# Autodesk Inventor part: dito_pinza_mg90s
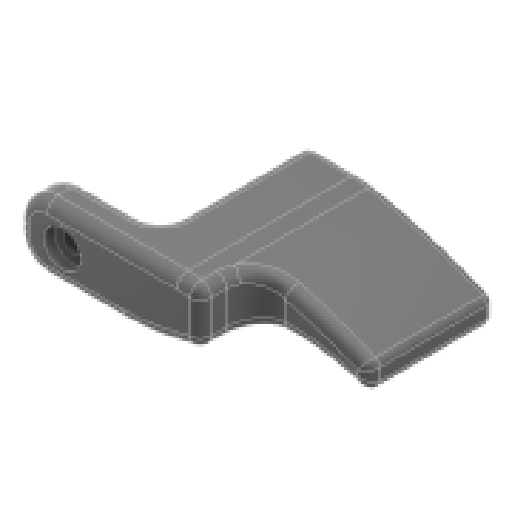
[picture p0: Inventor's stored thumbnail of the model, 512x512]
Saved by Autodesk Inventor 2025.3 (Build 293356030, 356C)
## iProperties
Created: 2026-03
Part Number: dito_pinza_mg90s
Material: Plastica ABS
Document SubType Name: Modeling
Designer: Ryzen5700u
Density: 1.06 g/cm^3
Appearance: Liscia - Nero
Author: Ryzen5700u
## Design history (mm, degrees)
sketch "Schizzo1"
  geometry: L1 (-6.045, 3.974)-(8.415, 2.335) reference; L2 (-12.5, -4.5)-(27.5, -4.5); L3 (27.5, -4.5)-(27.5, 4.5); L4 (27.5, 4.5)-(-12.5, 4.5); L5 (-12.5, 4.5)-(-12.5, -4.5); L6 (-6.5, 0)-(-16.812, 0); L7 (-4.9, 3)-(9.143, 1.995) reference; L8 (9.143, -1.995)-(-4.9, -3) reference; L9 (-4.889, 3.15)-(9.153, 2.145); L10 (9.153, -2.145)-(-4.889, -3.15); L11 (-12.5, -4.5)-(27.5, -4.5); L12 (27.5, -4.5)-(27.5, -5.5); L13 (27.5, -5.5)-(-12.5, -5.5); L14 (-12.5, -5.5)-(-12.5, -4.5); C1 r 3.55 at (-6.5, 0); A1 r 4 centre (-6.5, 0) between (-6.045, 3.974) and (-6.045, -3.974) reference; A2 r 3.4 centre (-6.5, 0) between (-4.9, 3) and (-4.9, -3); A3 r 2 centre (9, 0) between (9.143, -1.995) and (9.143, 1.995) reference; A4 r 2.15 centre (9, 0) between (9.153, -2.145) and (9.153, 2.145); 3 further points
  constraints: 26 end point, 4 centre point, 4 parallel, 4 point on circle, 3 horizontal, 2 perpendicular, 1 coincident, 11 other
  dimensions: "d1" = 40 distance of L4.end L3.end; "d4" = 9 distance of L2.end L3.end; "d35" = 6.8 diameter of A2; "d36" = 0.15 radial gap between concentric circles of A3 A4; "d37" = 0.15 radial gap between concentric circles of A2 C1; "d63" = 6 distance from line of L5 A1.centre; "d72" = 1 distance of L11.end L12.end
extrude "Estrusione1" new body sketch "Schizzo1" distance "d2" = 2; taper "d3" = 0 deg
sketch "Schizzo2"
  geometry: L1 (-12.5, 4.5)-(27.5, 4.5) reference; L2 (27.5, -4.5)-(-12.5, -4.5); L3 (-12.5, -4.5)-(-12.5, 4.5); L4 (-12.5, 4.5)-(27.5, 4.5); L5 (27.5, 4.5)-(27.5, -4.5); 2 further points
  constraints: 8 end point, 2 parallel, 1 horizontal, 1 perpendicular
node "Piano di lavoro1"
node "Piano di lavoro2"
extrude "Estrusione2" join sketch "Schizzo2" distance "d5" = 1.8; taper "d6" = 0 deg
hole "Foro3" sketch "Schizzo1" diameter "d28" = 2.7; stored, may be unused: countersink angle "d32" = 90 deg, drill point angle "d34" = 118 deg; dims "d29" = 6, "d30" = 5.5, "d31" = 2.9, "d33" = 8
fillet "Raccordo2" dims "d38" = 4
sketch "Schizzo5"
  geometry: L1 (-27.5, 4.5)-(8.5, 4.5) reference; L2 (-27.5, 4.5)-(-27.5, -4.5) reference; L3 (8.5, 4.5)-(-27.5, 4.5) reference; L4 (-27.5, 4.5)-(-27.5, -4.5) reference; L5 (-27.5, -4.5)-(8.5, -4.5) reference; L6 (12.5, -0.5)-(12.5, 0.5) reference; L7 (-9.153, 2.145)-(4.858, 3.147) reference; L8 (4.858, -3.147)-(-9.153, -2.145) reference; L9 (-27.5, -4.5)-(8.5, -4.5) reference; A1 r 74.354 centre (2.806, -68.708) between (15.809, 4.5) and (-27.5, -0.811); A2 r 4 centre (8.5, 0.5) between (12.5, 0.5) and (8.5, 4.5) reference; A3 r 4 centre (8.5, -0.5) between (8.5, -4.5) and (12.5, -0.5) reference; A4 r 2.15 centre (-9, 0) between (-9.153, 2.145) and (-9.153, -2.145) reference; A5 r 3.55 centre (6.5, 0) between (4.858, -3.147) and (4.858, 3.147) reference; A6 r 30 centre (-16.848, -32.545) between (-6.195, -4.5) and (-27.5, -4.5); 5 further points
  constraints: 4 point on circle, 4 point on line, 2 centre point
  dimensions: "d75" = 30 radius of A6
extrude "Estrusione3" cut sketch "Schizzo5" extent not by distance; stored distance "d39" = 1; taper "d40" = 0 deg
sketch "Schizzo6"
  geometry: C1 r 1.35 at (-6.5, 0) reference; 2 further points
  constraints: 1 coincident
hole "Foro4" sketch "Schizzo6" at (-6.5, 0) diameter "d41" = 2.7; stored, may be unused: countersink angle "d45" = 90 deg, drill point angle "d47" = 118 deg; dims "d42" = 6, "d43" = 5, "d44" = 0.5, "d46" = 8
fillet "Raccordo3" dims "d51" = 1
fillet "Raccordo4" dims "d52" = 30
sketch "Schizzo8"
  geometry: L1 (-1.657, -4.5)-(8.5, -4.5) reference; L2 (12.5, -0.5)-(12.5, 0.5) reference; L3 (8.5, 4.5)-(-10.197, 4.5) reference; L4 (-27.5, -1.463)-(-27.5, -3.086) reference; L5 (-9.153, 2.145)-(4.858, 3.147) reference; L6 (4.858, -3.147)-(-9.153, -2.145) reference; L7 (-2, 5.49)-(-2, -4.498); A1 r 30 centre (-1.657, 25.5) between (-9.252, -3.523) and (-1.657, -4.5) reference; A2 r 4 centre (8.5, -0.5) between (8.5, -4.5) and (12.5, -0.5) reference; A3 r 4 centre (8.5, 0.5) between (12.5, 0.5) and (8.5, 4.5) reference; A4 r 74.354 centre (2.806, -68.708) between (-10.197, 4.5) and (-26.9, -0.546) reference; A5 r 1 centre (-26.5, -1.463) between (-26.9, -0.546) and (-27.5, -1.463) reference; A6 r 1 centre (-26.5, -3.086) between (-27.5, -3.086) and (-26.189, -4.036) reference; A7 r 30 centre (-16.848, -32.545) between (-9.252, -3.523) and (-26.189, -4.036) reference; A8 r 2.15 centre (-9, 0) between (-9.153, 2.145) and (-9.153, -2.145) reference; A9 r 3.55 centre (6.5, 0) between (4.858, -3.147) and (4.858, 3.147) reference; 4 further points
  constraints: 2 end point, 2 point on circle, 1 vertical
  dimensions: "d53" = 2 distance from line of point (0, 0) L7
  node "Linea chiusa proiettata2"
node "Piano di lavoro3"
extrude "Estrusione4" join sketch "Schizzo8" distance "d54" = 5; taper "d55" = 0 deg
sketch "Schizzo9"
  geometry: L1 (-27.5, -1.463)-(-27.5, -3.086) reference; L2 (-2, -4.498)-(-2, -2.657) reference; L3 (-2, 4.202)-(-2, -4.498); L4 (-2, 4.5)-(-10.197, 4.5) reference; L5 (-2, -2.657)-(-9.153, -2.145) reference; L6 (-9.153, 2.145)-(-2, 2.657) reference; L7 (-2, 2.657)-(-2, 4.5) reference; A1 r 1 centre (-26.5, -3.086) between (-27.5, -3.086) and (-26.189, -4.036) reference; A2 r 30 centre (-16.848, -32.545) between (-9.252, -3.523) and (-26.189, -4.036) reference; A3 r 30 centre (-1.657, 25.5) between (-9.252, -3.523) and (-2, -4.498) reference; A4 r 74.354 centre (2.806, -68.708) between (-10.197, 4.5) and (-26.9, -0.546) reference; A5 r 1 centre (-26.5, -1.463) between (-26.9, -0.546) and (-27.5, -1.463) reference; A6 r 2.15 centre (-9, 0) between (-9.153, 2.145) and (-9.153, -2.145) reference; 6 further points
  constraints: 2 end point, 1 vertical
  node "Linea chiusa proiettata3"
node "Piano di lavoro4"
node "Piano di lavoro6"
extrude "Estrusione5" join sketch "Schizzo9" stored distance "d56" = 5; taper "d57" = 0 deg
fillet "Raccordo5" dims "d58" = 2
sketch "Schizzo10"
  geometry: L1 (27.5, -3.086)-(27.5, -1.463) reference; L2 (10.197, 4.5)-(-8.5, 4.5) reference; L3 (-12.5, 0.5)-(-12.5, -0.5) reference; L4 (-8.5, -4.5)-(1.657, -4.5) reference; L5 (2, 4.5)-(2, -4.498) reference; L6 (12.222, -2.904)-(12.222, 4.111); C1 r 2.5 at (-6.5, 0) reference; A1 r 30 centre (1.657, 25.5) between (1.657, -4.5) and (9.252, -3.523) reference; A2 r 30 centre (16.848, -32.545) between (26.189, -4.036) and (9.252, -3.523) reference; A3 r 1 centre (26.5, -3.086) between (26.189, -4.036) and (27.5, -3.086) reference; A4 r 1 centre (26.5, -1.463) between (27.5, -1.463) and (26.9, -0.546) reference; A5 r 74.354 centre (-2.806, -68.708) between (26.9, -0.546) and (10.197, 4.5) reference; A6 r 4 centre (-8.5, 0.5) between (-8.5, 4.5) and (-12.5, 0.5) reference; A7 r 4 centre (-8.5, -0.5) between (-12.5, -0.5) and (-8.5, -4.5) reference; 4 further points
  constraints: 2 end point, 2 point on circle, 1 vertical
  node "Linea chiusa proiettata4"
node "Piano di lavoro5"
extrude "Estrusione6" cut sketch "Schizzo10" stored distance "d59" = 5; taper "d60" = 0 deg
fillet "Raccordo6" dims "d61" = 4
fillet "Raccordo7" dims "d62" = 4
sketch "Schizzo11"
  geometry: L1 (25.5, 7.586)-(25.5, -1.412) reference; L2 (17.303, 7.586)-(25.5, 7.586) reference; L3 (0, 0)-(0, 1.624) reference; L4 (16.979, 11.31)-(28.224, 11.31); L5 (29.224, 10.31)-(29.224, 0.684); L6 (-3.724, -7.465)-(-3.724, 4.65); A1 r 74.354 centre (30.306, -65.622) between (17.303, 7.586) and (0.6, 2.54) reference; A2 r 1 centre (1, 1.624) between (0.6, 2.54) and (0, 1.624) reference; A3 r 1 centre (1, 0) between (0, 0) and (1.311, -0.95) reference; A4 r 30 centre (10.652, -29.459) between (18.248, -0.436) and (1.311, -0.95) reference; A5 r 30 centre (25.843, 28.586) between (18.248, -0.436) and (25.5, -1.412) reference; A6 r 78.078 centre (30.306, -65.622) between (16.979, 11.31) and (-3.724, 4.65); A7 r 5.724 centre (23.5, 0.684) between (23.021, -5.019) and (29.224, 0.684); A8 r 33.724 centre (25.843, 28.586) between (17.305, -4.039) and (23.021, -5.019); A9 r 26.276 centre (10.652, -29.459) between (17.305, -4.039) and (-3.724, -7.465); A10 r 1 centre (28.224, 10.31) between (29.224, 10.31) and (28.224, 11.31)
  constraints: 10 point on circle, 6 end point, 5 centre point, 2 tangent, 4 other
  dimensions: "d69" = 1 radius of A10
extrude "Estrusione7" cut sketch "Schizzo11" distance "d64" = 5; taper "d65" = 0 deg
fillet "Raccordo10" dims "d68" = 1
sketch "Schizzo12"
  geometry: L1 (-9.622, 2.058)-(-9.622, -2.058) reference; L2 (-9.153, -2.145)-(4.858, -3.147) reference; L3 (4.858, 3.147)-(-9.153, 2.145) reference; C1 r 1.35 at (6.5, 0) reference; A1 r 2.15 centre (-9, 0) between (-9.622, -2.058) and (-9.153, -2.145) reference; A2 r 3.55 centre (6.5, 0) between (4.858, -3.147) and (4.858, 3.147) reference; A3 r 2.15 centre (-9, 0) between (-9.153, 2.145) and (-9.622, 2.058) reference; 1 further point
extrude "Estrusione8" cut sketch "Schizzo12" distance "d73" = 4; taper "d74" = 0 deg
fillet "Raccordo13" dims "d76" = 2.5
fillet "Raccordo14" dims "d77" = 12
sketch "Schizzo13"
  geometry: L1 (0, 0)-(0, 1.624) reference; L2 (25.5, 7.586)-(25.5, -1.412) reference; L3 (18.407, 7.586)-(25.5, 7.586) reference; L4 (18.407, 5.786)-(23.5, 5.786); L5 (23.7, 5.586)-(23.7, 0.684); L6 (1.8, 1.084)-(1.8, 1.097); C1 r 0.75 at (9.384, 3.066); C2 r 0.55 at (23.15, 5.236); C3 r 0.511 at (23.189, 1.025); A1 r 12 centre (18.407, -4.414) between (18.407, 7.586) and (16.117, 7.366) reference; A2 r 74.354 centre (30.306, -65.622) between (16.117, 7.366) and (0.6, 2.54) reference; A3 r 1 centre (1, 1.624) between (0.6, 2.54) and (0, 1.624) reference; A4 r 1 centre (1, 0) between (0, 0) and (1.311, -0.95) reference; A5 r 30 centre (10.652, -29.459) between (18.248, -0.436) and (1.311, -0.95) reference; A6 r 30 centre (25.843, 28.586) between (18.248, -0.436) and (25.5, -1.412) reference; A7 r 72.554 centre (30.306, -65.622) between (16.461, 5.599) and (1.8, 1.097); A8 r 10.2 centre (18.407, -4.414) between (18.407, 5.786) and (16.461, 5.599); A9 r 0.2 centre (23.5, 5.586) between (23.7, 5.586) and (23.5, 5.786); A10 r 0.2 centre (23.5, 0.684) between (23.483, 0.485) and (23.7, 0.684); A11 r 28.2 centre (25.843, 28.586) between (18.704, 1.305) and (23.483, 0.485); A12 r 31.8 centre (10.652, -29.459) between (18.704, 1.305) and (1.8, 1.084); 7 further points
  constraints: 12 point on circle, 9 centre point, 6 end point, 6 tangent, 4 other
  dimensions: "d78" = 1.8 radial gap between concentric circles of A2 A7; "d81" = 1.5 diameter of C1
extrude "Estrusione9" cut sketch "Schizzo13" extent not by distance; stored distance "d79" = 0; taper "d80" = 0 deg
fillet "Raccordo15" dims "d82" = 1
fillet "Raccordo16" dims "d83" = 3
fillet "Raccordo17" dims "d84" = 1.5
sketch "Schizzo14"
  geometry: L1 (12.222, -2.904)-(12.222, 4.111) reference; L2 (9.093, 4.5)-(-8.5, 4.5) reference; L3 (-12.5, 0.5)-(-12.5, -0.5) reference; L4 (-8.5, -4.5)-(1.657, -4.5) reference; C1 r 2.5 at (-6.5, 0) reference; A1 r 74.354 centre (-2.806, -68.708) between (12.222, 4.111) and (11.383, 4.279) reference; A2 r 12 centre (9.093, -7.5) between (11.383, 4.279) and (9.093, 4.5) reference; A3 r 4 centre (-8.5, 0.5) between (-8.5, 4.5) and (-12.5, 0.5) reference; A4 r 4 centre (-8.5, -0.5) between (-12.5, -0.5) and (-8.5, -4.5) reference; A5 r 30 centre (1.657, 25.5) between (1.657, -4.5) and (9.252, -3.523) reference; A6 r 30 centre (16.848, -32.545) between (12.222, -2.904) and (9.252, -3.523) reference; 1 further point
extrude "Estrusione10" join sketch "Schizzo14" distance "d85" = 1; taper "d86" = 0 deg
fillet "Raccordo18" dims "d87" = 1.5
fillet "Raccordo19" dims "d88" = 1.5
sketch "Schizzo16"
  geometry: L1 (18.407, 7.586)-(24, 7.586) reference; L2 (0, 0)-(0, 1.624) reference; L3 (25.5, 6.086)-(25.5, 0.146) reference; L4 (18.407, 5.786)-(23.7, 5.786); L5 (23.7, 5.786)-(23.7, 0.468); L6 (1.8, 1.084)-(1.8, 1.097); C1 r 0.705 at (9.033, 3.005); C2 r 0.938 at (22.762, 4.848); C3 r 0.906 at (22.794, 1.463); A1 r 1.5 centre (24, 6.086) between (25.5, 6.086) and (24, 7.586) reference; A2 r 12 centre (18.407, -4.414) between (18.407, 7.586) and (16.117, 7.366) reference; A3 r 74.354 centre (30.306, -65.622) between (16.117, 7.366) and (0.6, 2.54) reference; A4 r 1 centre (1, 1.624) between (0.6, 2.54) and (0, 1.624) reference; A5 r 1 centre (1, 0) between (0, 0) and (1.311, -0.95) reference; A6 r 30 centre (10.652, -29.459) between (18.248, -0.436) and (1.311, -0.95) reference; A7 r 30 centre (25.843, 28.586) between (18.248, -0.436) and (23.903, -1.351) reference; A8 r 1.5 centre (24, 0.146) between (23.903, -1.351) and (25.5, 0.146) reference; A9 r 10.2 centre (18.407, -4.414) between (18.407, 5.786) and (16.461, 5.599); A10 r 28.2 centre (25.843, 28.586) between (18.704, 1.305) and (23.7, 0.468); A11 r 31.8 centre (10.652, -29.459) between (18.704, 1.305) and (1.8, 1.084); A12 r 72.554 centre (30.306, -65.622) between (16.461, 5.599) and (1.8, 1.097); 7 further points
  constraints: 8 point on circle, 7 centre point, 6 end point, 6 tangent, 6 other
  dimensions: "d89" = 1.8 radial gap between concentric circles of A2 A9
extrude "Estrusione11" cut sketch "Schizzo16" distance "d90" = 12; taper "d91" = 0 deg
fillet "Raccordo20" dims "d92" = 1.5
fillet "Raccordo21" dims "d93" = 1.5
node "Piano di lavoro7"
sketch "Schizzo17" dims "d95" = 7.4
  geometry: L1 (6.167, 3.685)-(-11.76, 2.065); L2 (3.715, 3.258)-(-2.04, 2.738) reference; L3 (6.5, 0)-(4.616, 0); L4 (6.167, -3.685)-(-11.76, -2.065); L5 (4.858, 3.147)-(-9.153, 2.145) reference; L6 (-9.153, -2.145)-(4.858, -3.147) reference; L7 (-9.153, 2.145)-(-9.153, -2.145); L8 (-11.76, 2.065)-(-11.76, -2.065); A1 r 1.1 centre (6.5, 0) between (6.5, -1.1) and (6.5, 1.1) reference; 7 further points
  constraints: 12 end point, 2 point on circle, 2 symmetric about line, 2 vertical, 1 centre point, 1 coincident, 1 horizontal, 1 parallel, 11 other
  dimensions: "d96" = 18 distance of L1.start L1.end
extrude "Estrusione12" cut sketch "Schizzo17" distance "d97" = 2; taper "d99" = 0 deg; dims "d98" = 2, "d100" = 0
fillet "Raccordo22" dims "d101" = 0.5
sketch "Schizzo18"
  geometry: L1 (-11.76, 2.065)-(6.167, 3.685) reference; L2 (-11.76, -2.065)-(-11.76, 2.065) reference; L3 (6.167, -3.685)-(-11.76, -2.065) reference; L4 (1.5, 3.263)-(1.5, -3.263); C1 r 1.35 at (6.5, 0) reference; A1 r 3.7 centre (6.5, 0) between (6.167, -3.685) and (6.167, 3.685) reference; 1 further point
  constraints: 2 end point, 2 point on line, 1 vertical
  dimensions: "d102" = 5 distance from line of A1.centre L4
extrude "Estrusione13" join sketch "Schizzo18" distance "d103" = 1; taper "d104" = 0 deg
sketch "Schizzo19"
  geometry: L1 (18.407, 5.786)-(22.762, 5.786) reference; L2 (23.7, 4.848)-(23.7, 1.463) reference; L3 (18.407, 7.586)-(24, 7.586) reference; L4 (0, 0)-(0, 1.624) reference; L5 (25.5, 6.086)-(25.5, 0.146) reference; A1 r 0.705 centre (9.033, 3.005) between (8.824, 3.679) and (9.068, 2.301) reference; A2 r 72.554 centre (30.306, -65.622) between (16.461, 5.599) and (8.824, 3.679) reference; A3 r 10.2 centre (18.407, -4.414) between (18.407, 5.786) and (16.461, 5.599) reference; A4 r 0.938 centre (22.762, 4.848) between (23.7, 4.848) and (22.762, 5.786) reference; A5 r 0.906 centre (22.794, 1.463) between (22.693, 0.563) and (23.7, 1.463) reference; A6 r 28.2 centre (25.843, 28.586) between (18.704, 1.305) and (22.693, 0.563) reference; A7 r 31.8 centre (10.652, -29.459) between (18.704, 1.305) and (9.068, 2.301) reference; A8 r 1.5 centre (24, 6.086) between (25.5, 6.086) and (24, 7.586) reference; A9 r 12 centre (18.407, -4.414) between (18.407, 7.586) and (16.117, 7.366) reference; A10 r 74.354 centre (30.306, -65.622) between (16.117, 7.366) and (0.6, 2.54) reference; A11 r 1 centre (1, 1.624) between (0.6, 2.54) and (0, 1.624) reference; A12 r 1 centre (1, 0) between (0, 0) and (1.311, -0.95) reference; A13 r 30 centre (10.652, -29.459) between (18.248, -0.436) and (1.311, -0.95) reference; A14 r 30 centre (25.843, 28.586) between (18.248, -0.436) and (23.903, -1.351) reference; A15 r 1.5 centre (24, 0.146) between (23.903, -1.351) and (25.5, 0.146) reference; 1 further point
extrude "Estrusione14" join sketch "Schizzo19" distance "d105" = 1; taper "d106" = 0 deg
fillet "Raccordo23" dims "d107" = 1
feature "ۣ耀ۥ耀ۧ耀۩耀۫耀ۭ耀ۯ耀۱耀" dims "d1" = 40, "d2" = 2, "d3" = 0, "d4" = 9, "d5" = 1.8, "d6" = 0, "d28" = 2.7, "d29" = 6, "d30" = 5.5, "d31" = 2.9, "d32" = 90 deg, "d33" = 8, "d34" = 118 deg, "d35" = 6.8, "d36" = 0.15, "d37" = 0.15, "d38" = 4, "d39" = 1, "d40" = 0, "d41" = 2.7, "d42" = 6, "d43" = 5, "d44" = 0.5, "d45" = 90 deg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
node "Solido1"
node "Linea chiusa proiettata1"
node "Linea chiusa proiettata6"
node "Linea chiusa proiettata7"
node "Linea chiusa proiettata8"
node "Linea chiusa proiettata9"
node "Linea chiusa proiettata10"
node "Linea chiusa proiettata11"
node "Linea chiusa proiettata12"
